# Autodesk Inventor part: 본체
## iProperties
Created: 2014-11
Part Number: 본체
Document SubType Name: Modeling
Designer: elite
Density: 2.71 g/cm^3
Material: 알루미늄-6061
Mass: 2878.98 g
Surface Area: 2087.15 cm^2
Volume: 1062.36 cm^3
Author: elite
